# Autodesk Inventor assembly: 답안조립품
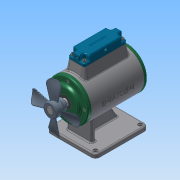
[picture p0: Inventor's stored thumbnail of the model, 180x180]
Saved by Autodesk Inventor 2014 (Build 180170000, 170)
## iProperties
Created: 2019-07
Part Number: 답안조립품
Document SubType Name: Assembly
Designer: net
Mass: 3408.14 g
Surface Area: 2825.58 cm^2
Volume: 1019.72 cm^3
Density: 3.34222 g/cm^3
Author: net
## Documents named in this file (19)
- C:\Users\net\Desktop\390704V1027\답안조립품.iam
- C:\Users\net\Desktop\390704V1027\뒤커버.ipt
- C:\Users\net\Desktop\390704V1027\멈춤나사 M4 x 5.ipt
- C:\Users\net\Desktop\390704V1027\베어링 6203.ipt
- C:\Users\net\Desktop\390704V1027\본체.ipt
- C:\Users\net\Desktop\390704V1027\볼트 M4 x 12.ipt
- C:\Users\net\Desktop\390704V1027\볼트 M4 x 16.ipt
- C:\Users\net\Desktop\390704V1027\부시.ipt
- C:\Users\net\Desktop\390704V1027\스프링 1.ipt
- C:\Users\net\Desktop\390704V1027\스프링 2.ipt
- C:\Users\net\Desktop\390704V1027\스프링 3.ipt
- C:\Users\net\Desktop\390704V1027\슬라이드.ipt
- C:\Users\net\Desktop\390704V1027\앞커버.ipt
- C:\Users\net\Desktop\390704V1027\오일실 17 30 8.ipt
- C:\Users\net\Desktop\390704V1027\축.ipt
- C:\Users\net\Desktop\390704V1027\키 5 x 5 x 18.ipt
- C:\Users\net\Desktop\390704V1027\팬날개.ipt
- 팬날개.ipt
- C:\Users\net\Desktop\390704V1027\헤더커버.ipt
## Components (1 placed, 1 different names)
1. 헤더커버:1 — 구동부
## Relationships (1: Angle 1)
- 구동부 [Angle]: 헤더커버:1
